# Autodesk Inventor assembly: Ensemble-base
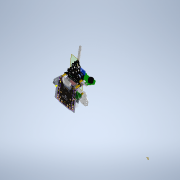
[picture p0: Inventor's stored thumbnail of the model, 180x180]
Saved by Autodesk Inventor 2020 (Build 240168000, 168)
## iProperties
Created: 2021-10
Part Number: Ensemble-base
Document SubType Name: Assembly
Designer: bruno
Mass: 96.2031 g
Surface Area: 854.612 cm^2
Volume: 85.8694 cm^3
Density: 1.12034 g/cm^3
Author: bruno
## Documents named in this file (12)
- C:\Users\bruno\OneDrive\Bureau\Robot-Inventor\Robot-equilibrage\Ensemble-base.iam
- C:\Users\bruno\OneDrive\Bureau\Robot-Inventor\Robot-equilibrage\base.ipt
- C:\Users\bruno\OneDrive\Bureau\Robot-Inventor\Robot-equilibrage\support-roue.ipt
- C:\Users\bruno\OneDrive\Bureau\Robot-Inventor\Robot-equilibrage\ecrou-hexa-2.ipt
- C:\Users\bruno\Documents\Inventor\Content Center Files\R2020\fr-FR\ANSI B18.6.7M(01)\ANSI B18.6.7M - M3x0,5 x 5(5).ipt
- C:\Users\bruno\OneDrive\Bureau\Robot-Inventor\Robot-equilibrage\pile.ipt
- C:\Users\bruno\OneDrive\Bureau\Robot-Inventor\Robot-equilibrage\microbit.ipt
- C:\Users\bruno\OneDrive\Bureau\Robot-Inventor\Robot-equilibrage\Ensemble-final.iam
- C:\Users\bruno\OneDrive\Bureau\Robot-Inventor\Robot-equilibrage\ecrou-hexa-3.ipt
- C:\Users\bruno\OneDrive\Bureau\Robot-Inventor\Robot-equilibrage\support-capteur.ipt
- C:\Users\bruno\OneDrive\Bureau\Robot-Inventor\Robot-equilibrage\capteur-ultrasons.ipt
- C:\Users\bruno\Documents\Inventor\Content Center Files\R2020\fr-FR\AS 1427(05)\AS 1427 - M3 x 5(5) II.ipt
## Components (19 placed, 11 different names)
1. base:1 — Placage:1, Placage:2, Placage:3, Placage:4, Placage:5, Placage:6, Placage:13, Placage:14, Placage:17, Placage:18, Placage:19, Affleurement:1, Logement:1, Logement:2, Logement:3
2. support-roue:1 — Placage:1, Placage:2, Affleurement:1
3. ecrou-hexa-2:1 — Placage:3, Placage:6, Placage:11
4. ecrou-hexa-2:2 — Placage:4, Placage:5, Placage:9, Placage:20
5. Vis à tête tronconique à empreinte cruciforme - Type IA - Métrique M3x0,5 x 5:1 — Placage:9, Tangente:1
6. Vis à tête tronconique à empreinte cruciforme - Type IA - Métrique M3x0,5 x 5:2 — Placage:11, Tangente:2
7. pile:1 — Placage:13, Placage:14
8. microbit:1 — Placage:17, Placage:18, Placage:19
9. Ensemble-final:1 [sub-assembly] — Placage:20, Tangente:1, Tangente:2
10. ecrou-hexa-3:1 — Logement:1, Logement:5
11. ecrou-hexa-3:2 — Logement:2
12. ecrou-hexa-3:3 — Logement:3, Logement:4
13. support-capteur:1 — Logement:4, Logement:5, Logement:6, Logement:7, Logement:8, Logement:9, Logement:10
14. capteur-ultrasons:1 — Logement:6, Logement:7, Logement:11, Logement:12
15. AS 1427 H - Métrique M3 x 5:1 — Logement:8
16. AS 1427 H - Métrique M3 x 5:2 — Logement:9
17. AS 1427 H - Métrique M3 x 5:3 — Logement:10
18. AS 1427 H - Métrique M3 x 5:4 — Logement:11
19. AS 1427 H - Métrique M3 x 5:5 — Logement:12
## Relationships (29: Mate 14, Insert 12, Tangent 2, Flush 1)
- Placage:1 [Mate]: base:1 ↔ support-roue:1
- Placage:2 [Mate]: base:1 ↔ support-roue:1
- Placage:3 [Mate]: base:1 ↔ ecrou-hexa-2:1
- Placage:4 [Mate]: base:1 ↔ ecrou-hexa-2:2
- Placage:5 [Mate]: base:1 ↔ ecrou-hexa-2:2
- Placage:6 [Mate]: base:1 ↔ ecrou-hexa-2:1
- Placage:9 [Mate]: ecrou-hexa-2:2 ↔ Vis à tête tronconique à empreinte cruciforme - Type IA - Métrique M3x0,5 x 5:1
- Placage:11 [Mate]: ecrou-hexa-2:1 ↔ Vis à tête tronconique à empreinte cruciforme - Type IA - Métrique M3x0,5 x 5:2
- Placage:13 [Mate]: base:1 ↔ pile:1
- Placage:14 [Mate]: base:1 ↔ pile:1
- Placage:17 [Mate]: base:1 ↔ microbit:1
- Placage:18 [Mate]: base:1 ↔ microbit:1
- Placage:19 [Mate]: base:1 ↔ microbit:1
- Affleurement:1 [Flush]: base:1 ↔ support-roue:1
- Logement:1 [Insert]: base:1 ↔ ecrou-hexa-3:1
- Logement:2 [Insert]: base:1 ↔ ecrou-hexa-3:2
- Logement:3 [Insert]: base:1 ↔ ecrou-hexa-3:3
- Logement:4 [Insert]: ecrou-hexa-3:3 ↔ support-capteur:1
- Logement:5 [Insert]: ecrou-hexa-3:1 ↔ support-capteur:1
- Logement:6 [Insert]: support-capteur:1 ↔ capteur-ultrasons:1
- Logement:7 [Insert]: support-capteur:1 ↔ capteur-ultrasons:1
- Logement:8 [Insert]: support-capteur:1 ↔ AS 1427 H - Métrique M3 x 5:1
- Logement:9 [Insert]: support-capteur:1 ↔ AS 1427 H - Métrique M3 x 5:2
- Logement:10 [Insert]: support-capteur:1 ↔ AS 1427 H - Métrique M3 x 5:3
- Logement:11 [Insert]: capteur-ultrasons:1 ↔ AS 1427 H - Métrique M3 x 5:4
- Logement:12 [Insert]: capteur-ultrasons:1 ↔ AS 1427 H - Métrique M3 x 5:5
- Placage:20 [Mate]: ecrou-hexa-2:2 ↔ Ensemble-final:1
- Tangente:1: Vis à tête tronconique à empreinte cruciforme - Type IA - Métrique M3x0,5 x 5:1 ↔ Ensemble-final:1
- Tangente:2: Vis à tête tronconique à empreinte cruciforme - Type IA - Métrique M3x0,5 x 5:2 ↔ Ensemble-final:1
